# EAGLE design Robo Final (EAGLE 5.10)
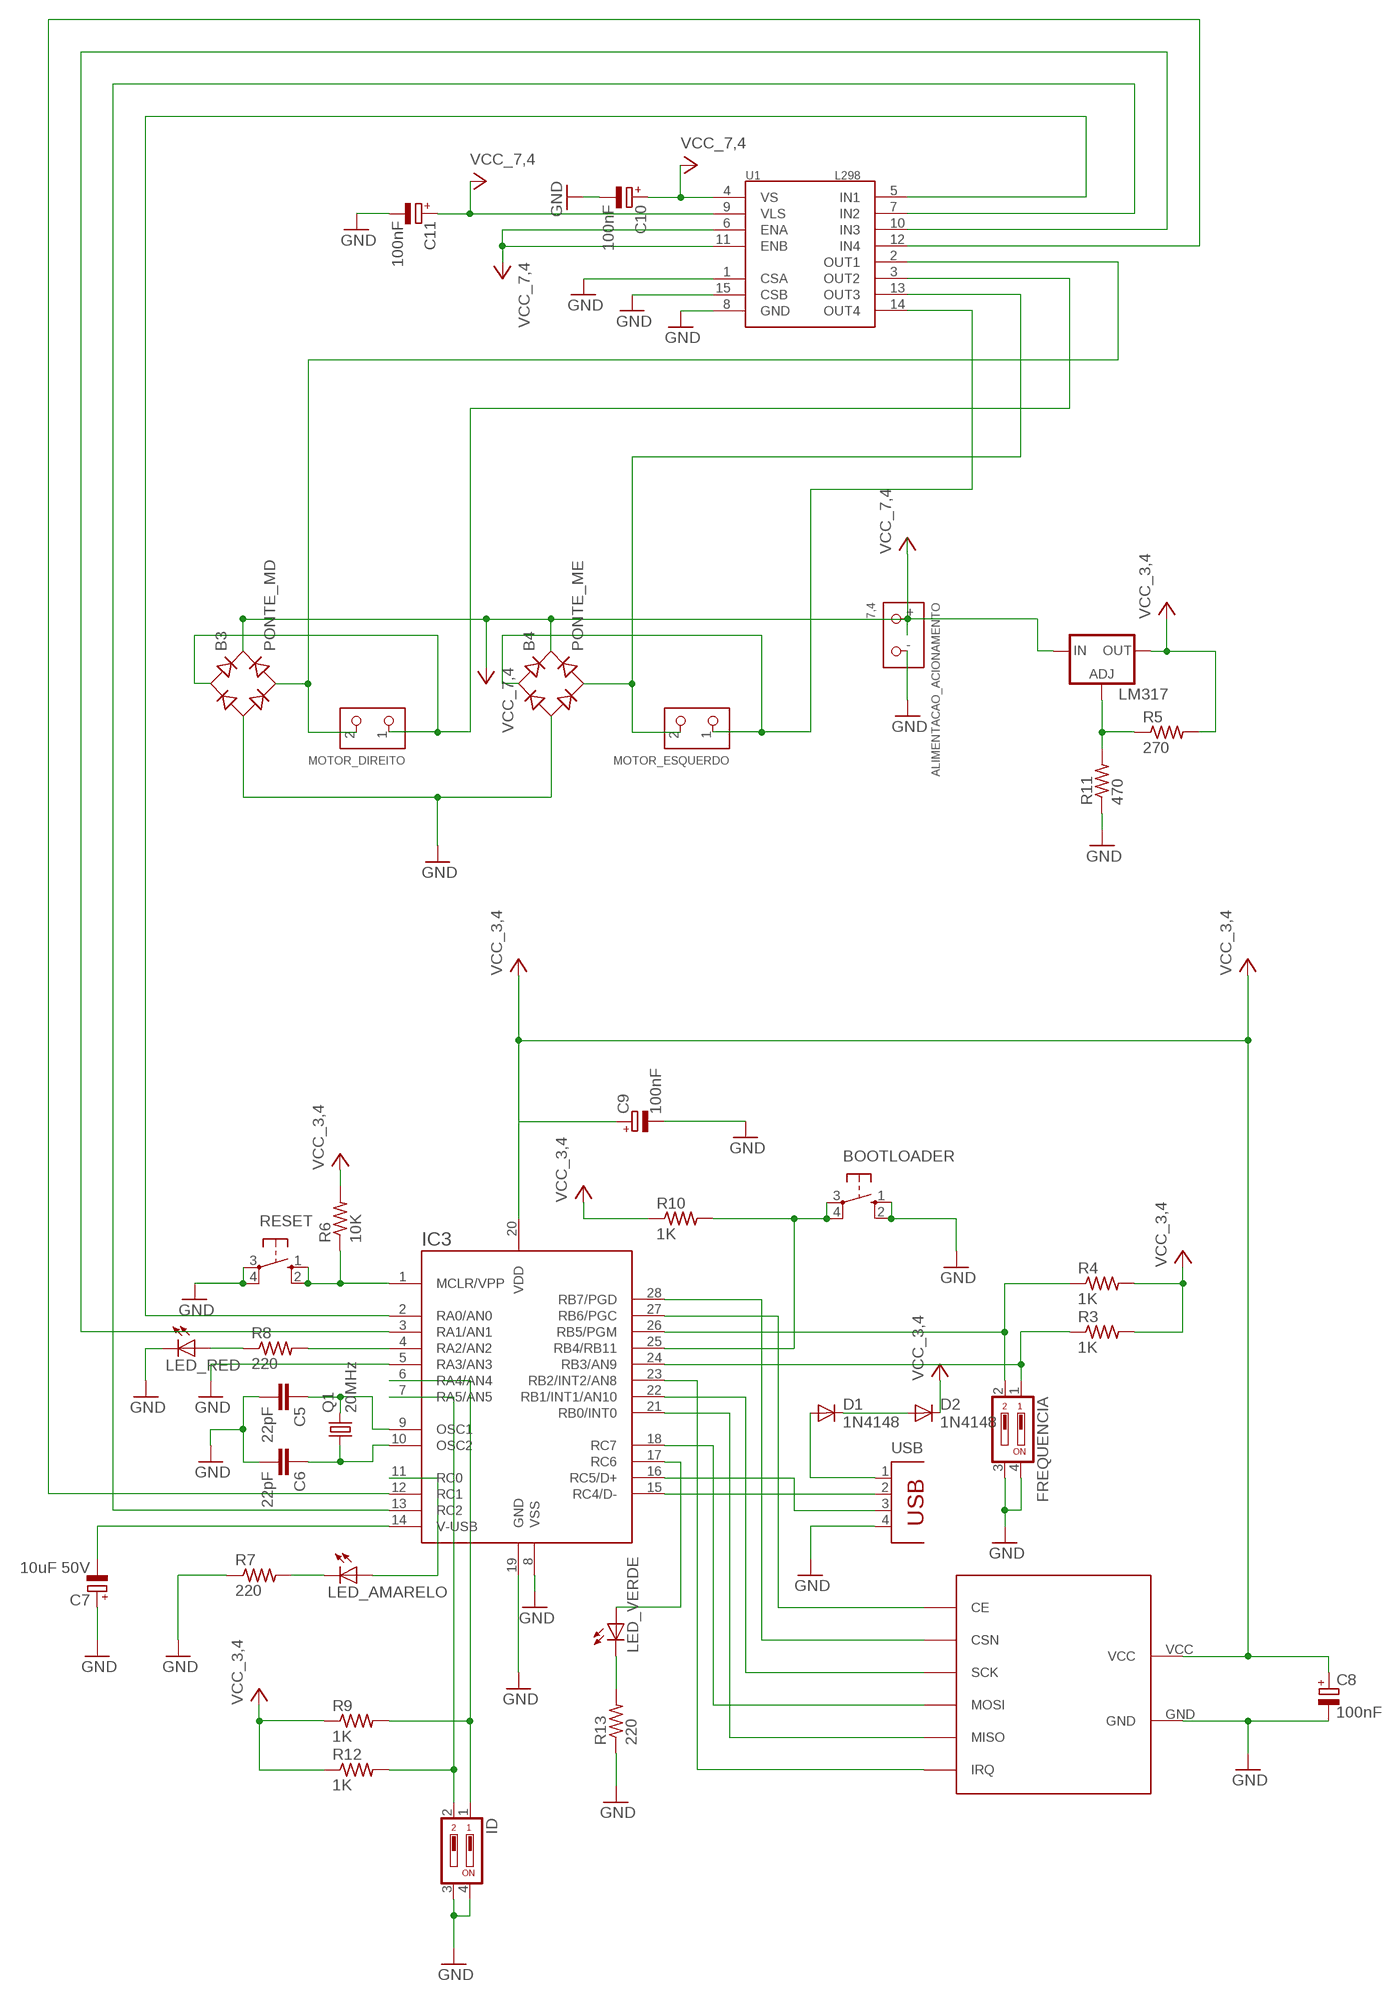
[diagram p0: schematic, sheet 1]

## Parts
ALIMENTACAO_ACIONAMENTO  7,4  PIN_HEADER/2_POWER  [22-04-1021/2-POWER]
B3  PONTE_MD  B-DIL  [B-DIL]
B4  PONTE_ME  B-DIL  [B-DIL]
BOOTLOADER  10-XX  [B3F-10XX]
C5  22pF  C2.5/2  [C2.5-2]
C6  22pF  C2.5/2  [C2.5-2]
C7  10uF 50V  CPOL-EUE3.5-10  [E3,5-10]
C8  100nF  CPOL-EUE2.5-6  [E2,5-6]
C9  100nF  CPOL-EUE2.5-6  [E2,5-6]
C10  100nF  CPOL-EUE2.5-6  [E2,5-6]
C11  100nF  CPOL-EUE2.5-6  [E2,5-6]
D1  1N4148  1N4148DO35-7  [DO35-7]
D2  1N4148  1N4148DO35-7  [DO35-7]
FREQUENCIA  DIP02YL  [DIP02YL]
IC3  PIC18F2550DIL-28  [DIL28]
ID  DIP02YL  [DIP02YL]
LED_AMARELO  LED3MM  [LED3MM]
LED_RED  LED3MM  [LED3MM]
LED_VERDE  LED3MM  [LED3MM]
LM317  LM317TS  [317TS]
MOTOR_DIREITO  PIN_HEADER/2  [22-04-1021/2]
MOTOR_ESQUERDO  PIN_HEADER/2  [22-04-1021/2]
NRF24L1  NFR24L01+  [NRF24L01_V2]
Q1  20MHz  CRYSTALHC49S  [HC49/S]
R3  1K  R-US_0207/7  [0207/7]
R4  1K  R-US_0207/7  [0207/7]
R5  270  R-US_0207/7  [0207/7]
R6  10K  R-US_0207/7  [0207/7]
R7  220  R-US_0207/7  [0207/7]
R8  220  R-US_0207/15  [0207/15]
R9  1K  R-US_0207/10  [0207/10]
R10  1K  R-US_0207/10  [0207/10]
R11  470  R-US_0207/7  [0207/7]
R12  1K  R-US_0207/7  [0207/7]
R13  220  R-US_0207/7  [0207/7]
RESET  10-XX  [B3F-10XX]
U1  L298  [MULTIWATT15]
USB  PN87520  [PN87520]

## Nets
CE: IC3.27(RB6/PGC) NRF24L1.CE
CSN: IC3.28(RB7/PGD) NRF24L1.CSN
FREQ1: FREQUENCIA.2 IC3.26(RB5/PGM) R4.1
FRQ0: FREQUENCIA.1 IC3.24(RB3/AN9) R3.1
GND: ALIMENTACAO_ACIONAMENTO.- B3.- B4.- BOOTLOADER.1(S) BOOTLOADER.2(S1) C5.2 C6.2 C7.+ C8.- C9.- C10.- C11.- FREQUENCIA.3 FREQUENCIA.4 IC3.5(RA3/AN3) IC3.8(VSS) IC3.19(GND) ID.3 ID.4 LED_RED.K(C) NRF24L1.GND R7.1 R11.1 R13.1 RESET.3(P) RESET.4(P1) U1.1(CSA) U1.8(GND) U1.15(CSB) USB.4
ID0: IC3.6(RA4/AN4) ID.1 R9.2
ID1: IC3.7(RA5/AN5) ID.2 R12.2
IRQ: IC3.23(RB2/INT2/AN8) NRF24L1.IRQ
MISO: IC3.21(RB0/INT0) NRF24L1.MISO
MOSI: IC3.18(RC7) NRF24L1.MOSI
N$1: IC3.4(RA2/AN2) R8.2
N$2(+): B4.AC1 MOTOR_ESQUERDO.1 U1.14(OUT4)
N$3(+): B3.AC1 MOTOR_DIREITO.1 U1.3(OUT2)
N$4: BOOTLOADER.3(P) BOOTLOADER.4(P1) IC3.25(RB4/RB11) R10.2
N$5: C7.- IC3.14(V-USB)
N$11: IC3.1(MCLR/VPP) R6.1 RESET.1(S) RESET.2(S1)
N$12(-): B4.AC2 MOTOR_ESQUERDO.2 U1.13(OUT3)
N$15: LM317.1(ADJ) R5.1 R11.2
N$16: C5.1 IC3.9(OSC1) Q1.2
N$17: IC3.15(RC4/D-) USB.2
N$18: C6.1 IC3.10(OSC2) Q1.1
N$19(-): B3.AC2 MOTOR_DIREITO.2 U1.2(OUT1)
N$20: IC3.16(RC5/D+) USB.3
N$21: IC3.12(RC1) U1.12(IN4)
N$24: IC3.13(RC2) U1.7(IN2)
N$25: D1.A USB.1
N$27: LED_AMARELO.K(C) R7.2
N$28: LED_VERDE.K(C) R13.2
N$29: IC3.11(RC0) LED_AMARELO.A
N$30: IC3.17(RC6) LED_VERDE.A
N$31: D1.C D2.A
N$43: LED_RED.A R8.1
SCK: IC3.22(RB1/INT1/AN10) NRF24L1.SCK
SENTIDO_DIREITO: IC3.2(RA0/AN0) U1.5(IN1)
SENTIDO_ESQUERDO: IC3.3(RA1/AN1) U1.10(IN3)
VCC_3,4: C8.+ C9.+ D2.C IC3.20(VDD) LM317.2(OUT) NRF24L1.VCC R3.2 R4.2 R5.2 R6.2 R9.1 R10.1 R12.1
VCC_7,4: ALIMENTACAO_ACIONAMENTO.+ B3.+ B4.+ C10.+ C11.+ LM317.3(IN) U1.4(VS) U1.6(ENA) U1.9(VLS) U1.11(ENB)

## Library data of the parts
ALIMENTACAO_ACIONAMENTO = Futebol_de_robos:PIN_HEADER/2_POWER: Connector de 2 pinos para alimentação
B3 B4 = rectifier:B-DIL: RECTIFIER
BOOTLOADER RESET = switch-omron:10-XX: OMRON SWITCH
C5 C6 = capacitor-wima:C: CAPACITOR
C7-C11 = rcl:CPOL-EU: POLARIZED CAPACITOR, European symbol
D1 D2 = diode:1N4148: DIODE
FREQUENCIA ID = switch-dil:DIP02YL: DIL/CODE SWITCH
IC3 = pic18f2550_3:PIC18F2550: PIC18F2550 Richard Myrick T. Arellaga April 2010
LED_AMARELO LED_RED LED_VERDE = led:LED: LED
LM317 = v-reg:LM317TS: VOLTAGE REGULATOR
MOTOR_DIREITO MOTOR_ESQUERDO = Futebol_de_robos:PIN_HEADER/2: Connector de 2 pinos
NRF24L1 = novo_transciever_v2:NFR24L01+: Transceiver nRF24L01+ para ser usado no futebol de robôs. Opera na faixa de 2.4 GHz.
Q1 = crystal:CRYSTAL: CRYSTAL
R3-R13 = resistor:R-US_: RESISTOR, American symbol
U1 = SparkFun_v2:L298: L298 Dual Full Bridge Driver
USB = con-berg:PN87520: BERG USB connector

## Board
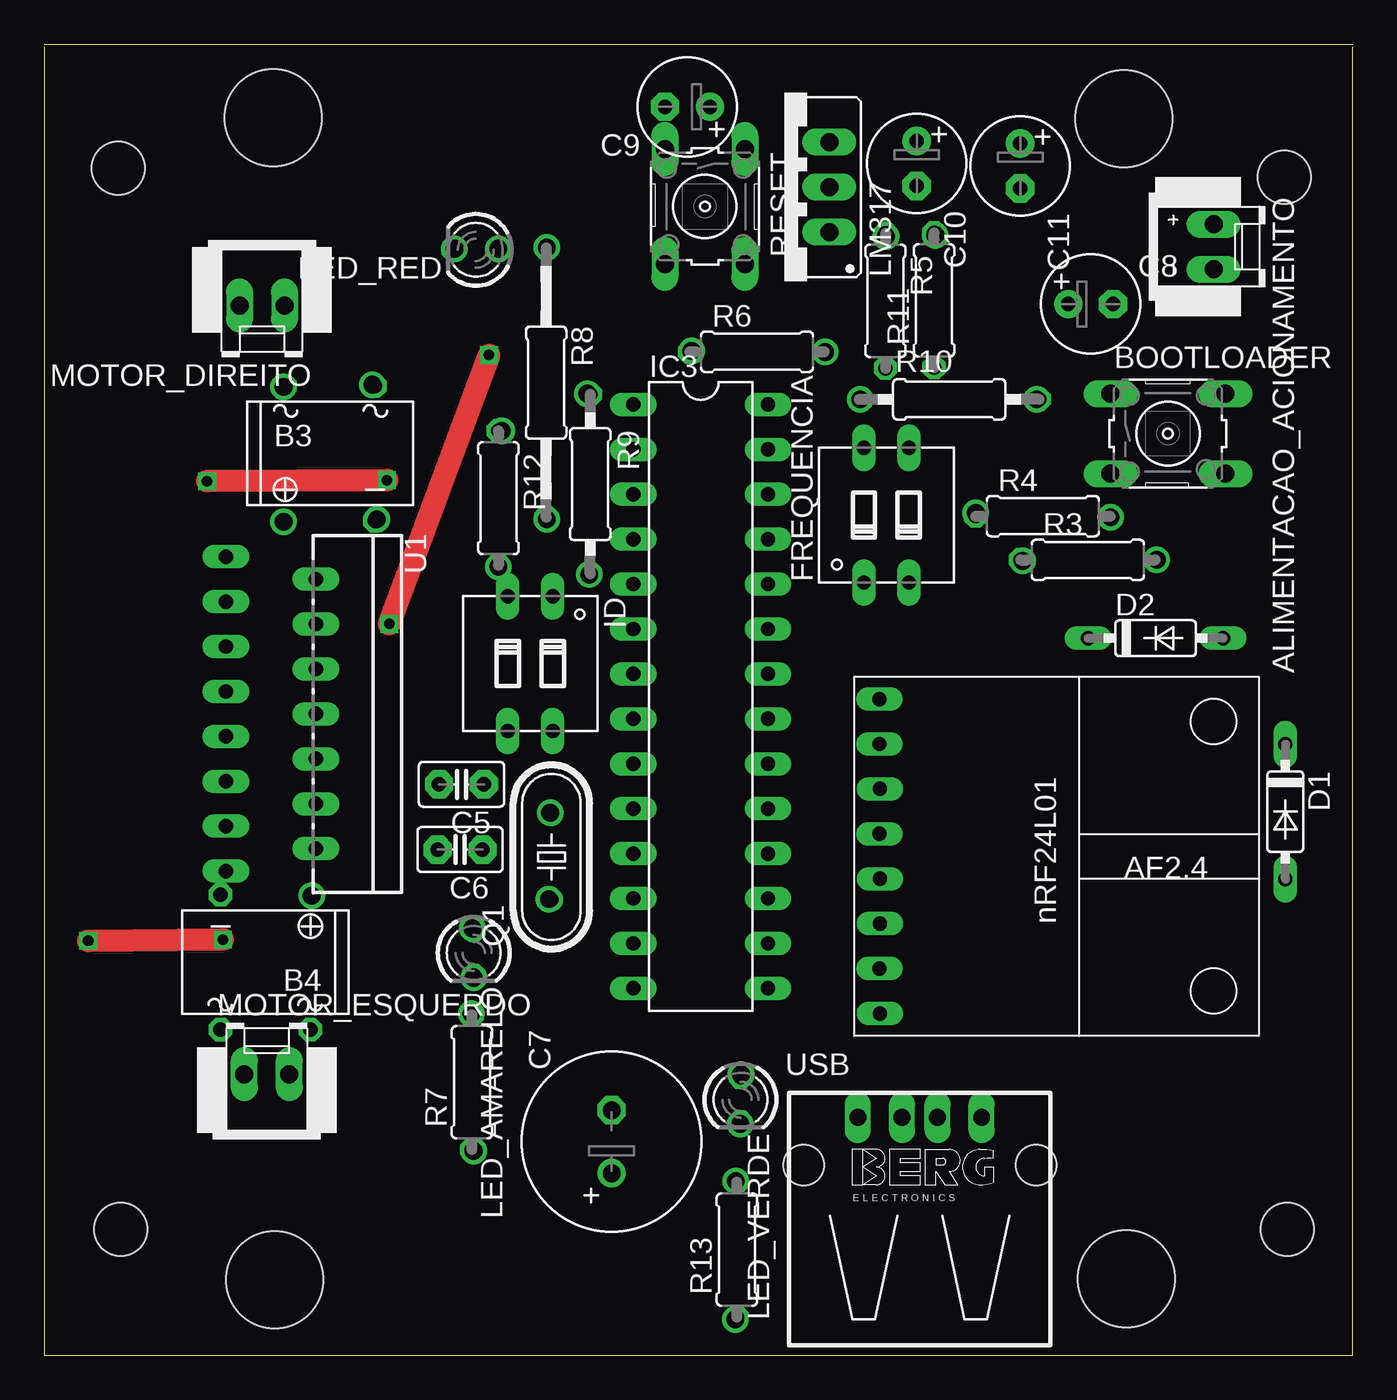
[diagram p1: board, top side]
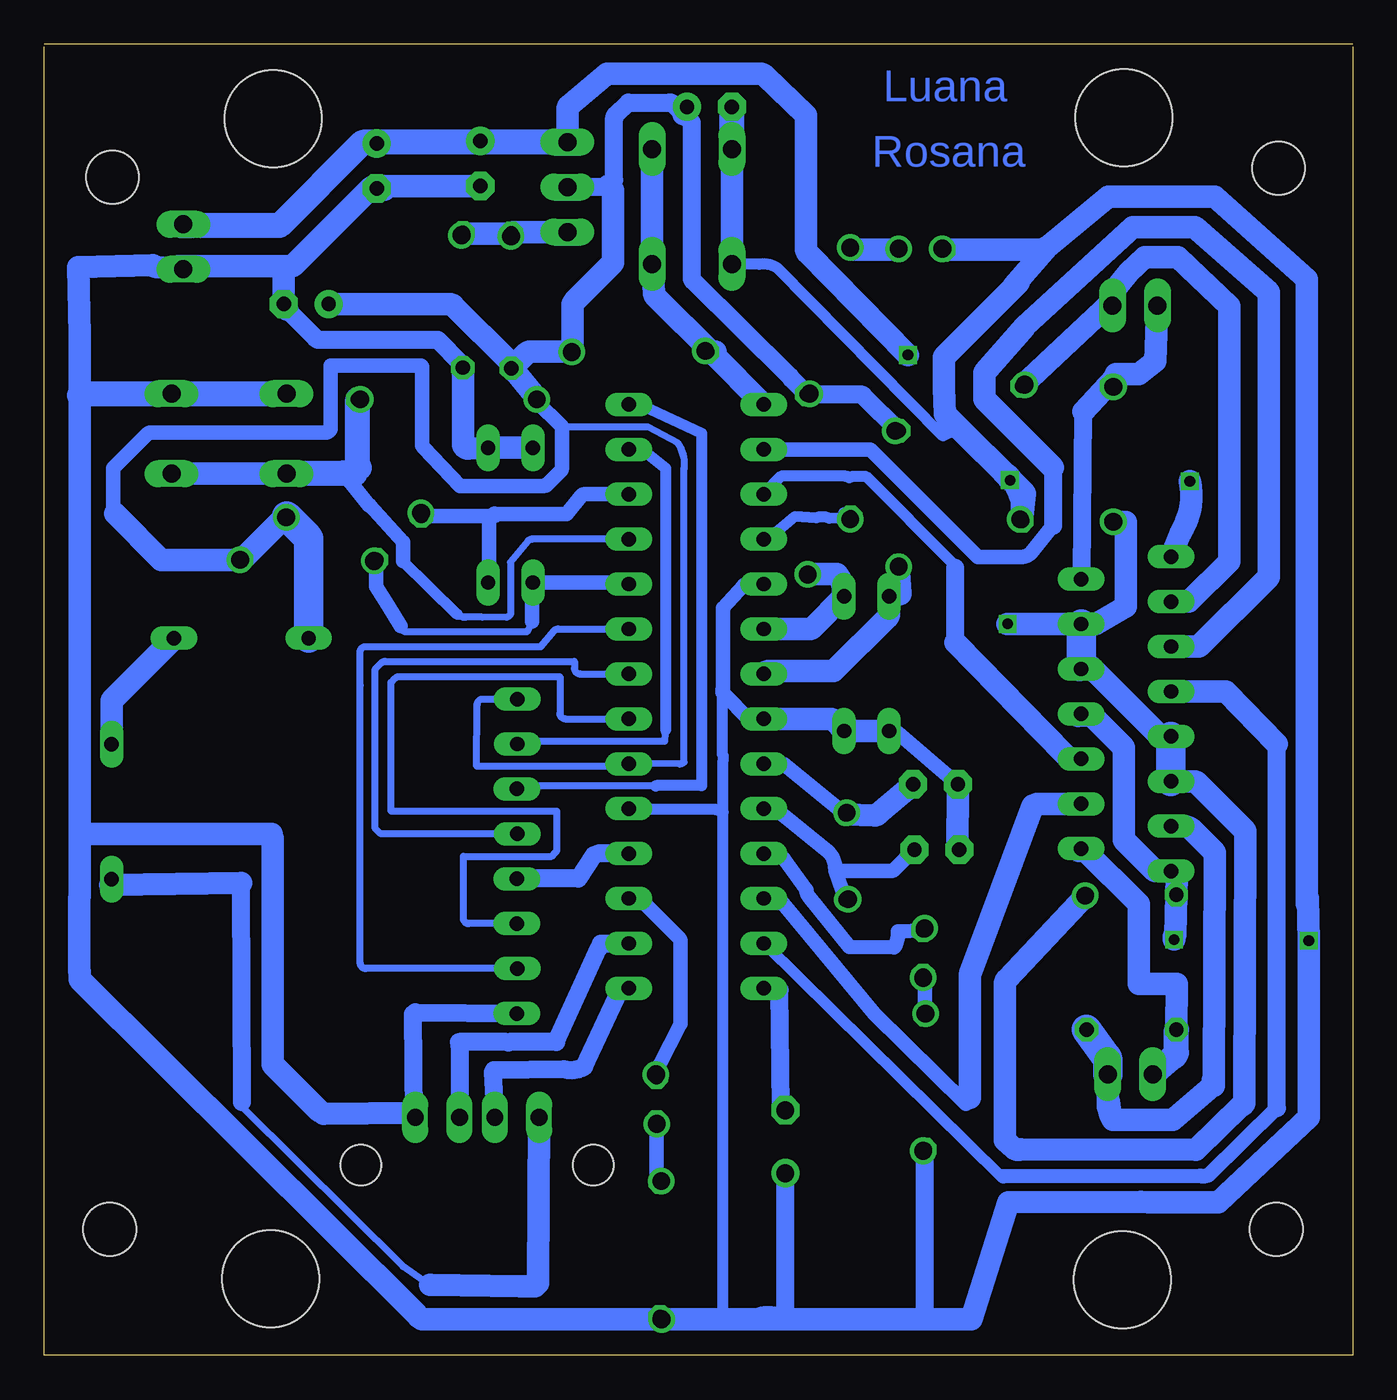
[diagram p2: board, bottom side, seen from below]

Size 74 x 74.15 mm. Coordinates in mm from the lower left corner, seen from the top.
Outline: 74,74 74,0 0,0 0,74
Outline: 0,74.15 74,74.15
Copper layers (1*16): Top 0.035mm / dielectric 1.5mm / Bottom 0.035mm
Design rules "default *": minimum track width 10mil, minimum drill 24mil, track to track 16mil, track to pad 16mil, pad to pad 16mil, via to via 16mil, smd to smd 8mil, copper to edge 40mil, drill to drill 8mil, minimum pad ring 10mil, minimum via ring 8mil, stop-mask expansion 4mil, vias tented up to drill 0mil, thermal gap 10mil
Holes 5.5 mm at 12.95,69.99 61.06,69.92 13.03,4.26 61.2,4.32
Holes 3 mm at 4.19,67.13 70.14,66.62 4.32,7.12 70.29,7.12

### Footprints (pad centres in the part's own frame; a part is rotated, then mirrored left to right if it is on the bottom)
22-04-1021/2-POWER = drill 1.016 pad 1.524 long: + -1.27,0; - 1.27,0
B-DIL = drill 0.813 round: + -2.54,-3.81 | drill 0.813 octagon: - 2.54,-3.81; AC1 2.54,3.81; AC2 -2.54,3.81
B3F-10XX = drill 1.016 long: 1 -3.251,2.261; 2 3.251,2.261; 3 -3.251,-2.261; 4 3.251,-2.261
C2.5-2 = drill 0.813 pad 1.6 octagon: 1 -1.27,0; 2 1.27,0
E3,5-10 = drill 0.813 pad 1.6 round: + -1.778,0 | drill 0.813 pad 1.6 octagon: - 1.778,0
E2,5-6 = drill 0.813 pad 1.6 round: + -1.27,0 | drill 0.813 pad 1.6 octagon: - 1.27,0
DO35-7 = drill 0.813 long: A 3.81,0; C -3.81,0
DIP02YL = drill 0.813 long: 1 -1.27,-3.81; 2 1.27,-3.81; 3 1.27,3.81; 4 -1.27,3.81
DIL28 = drill 0.813 long: 1 -16.51,-3.81; 2 -13.97,-3.81; 3 -11.43,-3.81; 4 -8.89,-3.81; 5 -6.35,-3.81; 6 -3.81,-3.81; 7 -1.27,-3.81; 8 1.27,-3.81; 9 3.81,-3.81; 10 6.35,-3.81; 11 8.89,-3.81; 12 11.43,-3.81; 13 13.97,-3.81; 14 16.51,-3.81; 15 16.51,3.81; 16 13.97,3.81; 17 11.43,3.81; 18 8.89,3.81; 19 6.35,3.81; 20 3.81,3.81; 21 1.27,3.81; 22 -1.27,3.81; 23 -3.81,3.81; 24 -6.35,3.81; 25 -8.89,3.81; 26 -11.43,3.81; 27 -13.97,3.81; 28 -16.51,3.81
LED3MM = drill 0.813 octagon: A -1.27,0; K 1.27,0
317TS = drill 1.016 long: 1 -2.54,-2.54; 2 0,-2.54; 3 2.54,-2.54
22-04-1021/2 = drill 1.016 pad 1.524 long: 1 -1.27,0; 2 1.27,0
NRF24L01_V2 = drill 0.813 long: CE 1.422,16.51; CSN 1.448,13.97; GND 1.448,1.27; IRQ 1.422,3.81; MISO 1.448,6.35; MOSI 1.448,8.89; SCK 1.422,11.43; VCC 1.422,19.05
HC49/S = drill 0.813 round: 1 -2.413,0; 2 2.413,0
0207/7 = drill 0.813 octagon: 1 -3.81,0; 2 3.81,0
0207/15 = drill 0.813 octagon: 1 -7.62,0; 2 7.62,0
0207/10 = drill 0.813 octagon: 1 -5.08,0; 2 5.08,0
MULTIWATT15 = drill 0.813 long: 1 -8.95,-2.39; 2 -7.68,2.69; 3 -6.41,-2.39; 4 -5.14,2.69; 5 -3.87,-2.39; 6 -2.6,2.69; 7 -1.33,-2.39; 8 -0.06,2.69; 9 1.21,-2.39; 10 2.48,2.69; 11 3.75,-2.39; 12 5.02,2.69; 13 6.29,-2.39; 14 7.56,2.69; 15 8.83,-2.39
PN87520 = drill 0.95 long: 1 -3.5,2.71; 2 -1,2.71; 3 1,2.71; 4 3.5,2.71 | hole 2.3: -6.57,0; 6.57,0

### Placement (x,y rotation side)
ALIMENTACAO_ACIONAMENTO  66.14,62.69 270 top
B3  16.17,51 0 top
B4  12.51,22.24 180 top
BOOTLOADER  63.55,52.12 0 top
C5  23.6,32.29 180 top
C6  23.52,28.6 180 top
C7  32.08,12.08 90 top
C8  59.18,59.45 0 top
C9  36.38,70.61 180 top
C10  49.34,67.4 270 top
C11  55.2,67.26 270 top
D1  70.19,30.74 270 top
D2  62.85,40.55 0 top
FREQUENCIA  47.63,47.51 0 top
IC3  37.12,37.26 270 top
ID  27.49,39.12 180 top
LED_AMARELO  24.29,22.76 270 top
LED_RED  24.41,62.52 180 top
LED_VERDE  39.38,14.46 270 top
LM317  41.87,66.07 90 top
MOTOR_DIREITO  12.32,59.37 180 top
MOTOR_ESQUERDO  12.59,15.89 0 top
NRF24L1  45.81,18.06 0 top
Q1  28.68,28.19 90 top
R3  59.02,44.98 0 top
R4  56.48,47.46 0 top
R5  47.57,59.63 270 top
R6  40.31,56.75 0 top
R7  24.19,15.44 90 top
R8  28.38,55.01 270 top
R9  30.88,49.27 270 top
R10  51.18,54.06 0 top
R11  50.32,59.66 90 top
R12  25.69,48.47 270 top
R13  39.17,5.98 90 top
RESET  37.37,64.97 270 top
U1  12.67,36.21 270 top
USB  49.51,10.74 0 top

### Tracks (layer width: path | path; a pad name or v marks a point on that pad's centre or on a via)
CE
  Bottom 0.4: 38.91,34.72 47.25,34.72
  Bottom 0.406: 47.25,34.72 47.25,34.58 arc-90 NRF24L1.CE | 38.84,35.37 arc-90 38.9,35.19 38.91,34.72
  Bottom 0.61: IC3.27 40.31,51.23 arc45 40.09,51.14 38.84,50.16 38.84,35.37
CSN
  Bottom 0.4: 39.42,32.19 46.5,32.19
  Bottom 0.406: NRF24L1.CSN 46.79,32.03 arc-45 46.56,32.12 46.5,32.19
  Bottom 0.61: IC3.28 40.36,53.77 arc45 40.13,53.68 36.8,52.13 36.8,32.28 arc45 36.83,32.22 39.35,32.22 arc-45 39.42,32.19
FREQ1
  Bottom 0.813: 48.6,47.55 48.85,47.31 48.85,43.83 arc45 FREQUENCIA.2 | IC3.26 43.41,48.69 arc-45 43.63,48.6 44.46,47.59 45.38,47.59 arc47 45.44,47.59 48.31,47.59 arc-45 48.47,47.49 48.54,47.62 48.6,47.55 | R4.1 48.83,47.46 arc-45 48.6,47.55
FRQ0
  Bottom 0.406: 46.41,41.5 46.71,40.91 51.66,40.91 53.52,40.91 arc90 53.84,41.23
  Bottom 0.813: IC3.24 arc-45 41.15,43.7 FREQUENCIA.1 arc-90 46.41,43.65 46.41,41.5 | R3.1 arc-45 55.22,44.96 55.22,43.47 54.54,42.39 53.84,41.23
GND  (via drill 0.6)
  Top 1.27: v19.38,49.49 v9.21,49.43 | v2.49,23.44 v10.1,23.51
  Bottom 0.406: 53.14,19.3 arc45 53,19.39 | USB.4 arc-45 53.07,13.47
  Bottom 0.61: RESET.4 33.56,61.7 arc45 32.54,61.48 23.17,51.99 22.27,52.38 arc45 23.1,54.47 23.12,54.69 | 35.64,37.47 35.64,33.99 arc45 35.61,33.64 35.61,30.7 | IC3.19 arc-45 40.81,30.86 36.02,30.86 arc45 35.8,30.77 35.61,30.7 | 35.61,30.7 35.61,2.34 arc45 35.83,2.11 35.91,2.03
  Bottom 0.813: 33.17,35.93 arc45 IC3.8 33.33,35.98 arc45 33.55,35.88 34.06,35.88 35.64,37.47 arc45 35.61,37.69 35.61,42.25 34.46,43.52 arc45 34.24,43.61 IC3.5 | C5.2 25.76,35.22 arc-45 25.98,35.31 ID.3 | 58.42,13.8 arc-45 58.2,13.65 | 61.14,29.48 arc45 61.08,29.26 | 72,29.48 arc-53 71.85,29.48
  Bottom 1.016: U1.8 15.52,36.11 15.52,36.02 | 60.27,59.14 58.66,57.52 arc-45 58.43,57.43 51.75,57.43 50.42,56.09 arc45 50.32,55.87 R11.1 | C7.+ 32.08,2.03 arc-45 33.58,2.2 33.41,2.03 | R7.1 24.19,2.24 arc45 24.28,2.03 | R13.1 41.23,2.07 arc-45 41.22,2.03 | 53,19.39 NRF24L1.GND | 53.07,13.47 53.14,19.3
  Bottom 1.27: 17.27,62.66 13.81,65.53 7.79,65.53 2.6,60.85 2.6,25.53 arc-45 2.55,25.86 v2.49,23.44 2.49,13.46 7.61,8.65 11.57,8.65 11.98,8.69 19.46,8.65 21.58,2.03 24.28,2.03 33.41,2.03 35.91,2.03 41.22,2.03 52.58,2.03 arc45 52.94,2.32 71.99,21.25 71.98,21.67 arc-45 72.01,21.72 72.01,25.88 72,25.95 72,29.48 72,54.3 72,57.7 72.09,61.55 67.87,61.64 arc-45 67.64,61.55 ALIMENTACAO_ACIONAMENTO.- arc45 66.41,61.6 60.41,61.6 | 17.27,62.66 19.17,60.5 18.86,60.7 23.12,56.44 23.12,54.69 23.06,53.23 18.55,48.72 B3.- 18.71,48.25 arc-45 19.95,50.12 v19.38,49.49 | 15.33,36.24 U1.8 15.27,36.18 14.74,36.18 12.93,34.38 12.93,29.13 11.18,27.38 U1.15 9.94,27.04 B4.- 10.04,23.76 arc-90 v10.1,23.51 | 26.15,35.28 arc-45 ID.3 ID.4 29.35,35.9 arc-45 29.57,35.99 IC3.8 | C6.2 22.32,28.65 arc-45 22.36,28.5 C5.2 | RESET.4 RESET.3 | LED_RED.K 17.5,62.52 arc45 17.27,62.66 | 54.84,66.13 arc-45 54.74,65.91 C11.- | C10.- 54.91,66.13 arc-45 C11.- | C11.- 55.3,66.11 arc-45 55.52,66.02 59.95,61.6 60.41,61.6 | R11.1 50.32,51.59 arc-90 50.01,51.28 FREQUENCIA.3 FREQUENCIA.4 | 60.41,61.6 arc-45 60.45,61.5 C8.- 60.37,59.36 arc45 60.27,59.14 | v9.21,49.43 arc45 9.75,46.48 U1.1 | 58.2,13.65 53.13,13.72 53.13,13.51 arc-90 USB.4 | 58.42,13.8 61.08,16.45 61.08,29.26 | 71.85,29.48 61.14,29.48
  Bottom 1.422: C9.- arc45 35.1,70.6 RESET.3 | BOOTLOADER.1 BOOTLOADER.2 71.8,54.38 arc-45 72,54.3
ID0
  Bottom 1.27: R9.2 29.17,44.17 arc45 28.82,43.19 ID.1 30.52,41.17 arc45 30.75,41.07 IC3.6
ID1
  Bottom 1.27: R12.2 25.58,43.06 arc45 26.12,43.03 ID.2 26.22,41.96 arc45 26.31,41.73 29.36,38.69 33.03,38.69 arc-45 33.25,38.6 IC3.7
IRQ
  Bottom 0.406: IC3.23 44.93,41.07 arc-45 45.16,40.98 45.92,40.08 55.82,40.08 arc-90 56.14,39.76 56.14,39.7 56.13,37.89 56.13,22.19 arc-90 55.81,21.87 NRF24L1.IRQ
MISO
  Bottom 0.4: 50.3,28.22 45.3,28.22 | 45.55,30.76 50.45,30.76
  Bottom 0.406: NRF24L1.MISO 49.98,24.41 arc90 50.3,24.73 50.3,28.22 | IC3.21 44.52,35.99 arc90 44.84,36.31 44.84,38.38 53.92,38.38 arc-45 54.15,38.29 54.38,38.05 54.38,30.8 arc-45 54.28,30.76 50.45,30.76 | 45.55,30.76 45.01,30.77 45.01,28.65 arc45 45.1,28.43 45.3,28.22
MOSI
  Bottom 0.406: 42.7,28.37 arc-45 42.92,28.28 | 47.08,26.96 arc45 NRF24L1.MOSI
  Bottom 1.016: IC3.18 42.7,28.37 | 42.92,28.28 43.78,26.96 47.08,26.96
N$1
  Bottom 0.61: 28.79,47.66 arc45 28.56,47.56 R8.2 29.6,47.33 arc-45 30.33,47.36 31.56,47.42 32.99,46.25 arc45 33.22,46.15 IC3.4
N$2  (via drill 0.6 pad 5.5)
  other vias: 61.06,69.94
N$2(+)
  Bottom 1.27: B4.AC1 9.94,21.01 12.09,21 12.1,25.53 15.19,28.61 15.5,28.51 U1.14
  Bottom 1.422: B4.AC1 9.97,17.11 arc45 10.13,16.89 MOTOR_ESQUERDO.1
N$3  (via drill 1)
  other vias: 28.42,62.64
N$3(+)
  Bottom 1.27: U1.3 9.27,42.62 6.99,44.9 6.99,59.33 9.9,62.1 11.75,62.1 12.66,61.27 13.52,60.21 MOTOR_DIREITO.1 13.69,59.52 B3.AC1
N$4
  Bottom 0.406: IC3.25 46.41,46.15 arc-45 46.63,46.06 47.63,44.85 47.63,41.9 arc45 47.86,41.73 49.24,41.74 50.14,41.74 arc45 50.64,41.9 | 55.6,48.09 arc45 55.63,48.07 | 53.74,44.91 arc-45 53.7,44.92
  Bottom 0.61: 50.64,41.9 53.74,44.91
  Bottom 0.813: 55.63,48.07 57.09,49.89 | 55.6,48.09 53.7,46 53.7,44.92
  Bottom 1.27: BOOTLOADER.3 BOOTLOADER.4
  Bottom 1.422: BOOTLOADER.3 56.43,49.86 arc45 56.78,49.83 | 57.09,49.89 56.78,49.83 | R10.2 56.26,50.41 arc-45 56.17,50.18 56.78,49.83
N$5
  Bottom 0.406: 32.41,20.66 arc-45 32.51,20.75
  Bottom 0.813: 32.51,20.75 IC3.14
  Bottom 1.016: C7.- 32.34,14.01 32.41,20.66
N$6  (via drill 0.6 pad 3)
  other vias: 70.15,66.63
N$7  (via drill 0.6 pad 5.5)
  other vias: 13.04,4.26
N$8  (via drill 0.6 pad 5.5)
  other vias: 61.2,4.32
N$9  (via drill 0.6 pad 5.5)
  other vias: 12.96,70
N$10  (via drill 0.6 pad 3)
  other vias: 4.31,7.13
N$11
  Bottom 1.27: IC3.1 36.21,56.67 | 36.21,56.67 39.42,59.88 arc45 39.51,60.1 RESET.2 RESET.1 | R6.1 36.03,56.75 arc-45 36.21,56.67
N$12  (via drill 0.6 pad 3)
  other vias: 4.15,67.12
N$12(-)
  Bottom 1.27: U1.13 9.54,29.92 arc45 9.08,29.71 7.81,28.44 7.85,15.23 7.91,15.59 arc45 8.01,15.17 10.18,13.32 13.57,13.32 arc44 13.8,14.37 13.75,13.92 13.76,13.94 arc45 13.86,14.16 MOTOR_ESQUERDO.2
  Bottom 1.676: MOTOR_ESQUERDO.2 13.86,16.68 arc-45 13.95,16.91 B4.AC2
N$13  (via drill 0.6 pad 3)
  other vias: 70.31,7.14
N$14  (via drill 1)
  other vias: 25.69,62.58
N$15
  Bottom 1.27: LM317.1 47.38,63.53 arc-45 R5.1 50.26,63.44 arc45 R11.2
N$16
  Bottom 0.813: Q1.2 32.08,33.36 arc-45 32.31,33.45 IC3.9
  Bottom 1.27: C5.1 26.83,30.63 arc45 27.05,30.54 Q1.2
N$17
  Bottom 0.406: 41.43,20.66 arc45 41.21,20.75 | 48.56,16.12 arc-45 48.64,16.01
  Bottom 1.016: 41.21,20.75 IC3.15 | 41.43,20.66 43.47,16.32 arc45 44.61,16.18 48.56,16.12 | 48.64,16.01 USB.2
N$18
  Bottom 0.813: 33.2,30.96 arc-45 IC3.10 arc45 33.29,30.93 32.66,30.93 29.67,28.5 arc45 29.26,27.39 | 29.26,27.39 Q1.1 | 29.26,27.39 26.13,27.39 arc-45 25.91,27.48 C6.1
N$19  (via drill 1)
  other vias: 23.21,62.58
N$19(-)
  Bottom 1.016: 15.32,44.09 15.23,53.37
  Bottom 1.27: U1.2 15.33,43.89 arc-90 15.32,44.09 | MOTOR_DIREITO.2 11.17,56.21 12.09,55.48 13.4,55.48 B3.AC2 13.47,55.26 15.23,53.37
N$20
  Bottom 0.406: 42.62,23.06 arc-45 42.53,23.28 | 50.55,17.71 arc-45 50.52,17.52 | 47.76,17.67 arc45 47.85,17.71
  Bottom 1.016: 42.53,23.28 IC3.16 | 42.62,23.06 45.05,17.71 47.72,17.71 47.76,17.67 | 50.52,17.52 USB.3 | 47.85,17.71 50.55,17.71
N$21
  Bottom 0.813: 18.08,31.1 arc45 17.86,31.19 | IC3.12 33.15,25.67 arc-45 32.93,25.58 32.52,25.58 arc45 32.23,25.55 27.06,19.29 21.88,14.21 21.75,14.34 arc-45 21.66,14.57
  Bottom 1.27: 17.86,31.19 U1.12 | 18.08,31.1 21.66,21.55 21.66,14.57
N$22  (via drill 1)
  other vias: 24.29,11.56
N$23  (via drill 1)
  other vias: 24.16,19.31
N$24
  Bottom 0.61: 32.8,23.05 32.94,23.05 arc45 33.17,23.15 IC3.13 | 19.77,10.12 arc-45 19.83,10.07 33.2,23.25 arc-45 IC3.13 | 32.98,23.1 arc45 33.21,23.19 IC3.13
  Bottom 0.813: 4.29,13.99 8.12,10.21 arc45 8.64,10.15 19.77,10.12
  Bottom 1.016: 4.29,13.99 4.29,34.56
  Bottom 1.27: U1.7 7.18,37.54 4.29,34.56
N$25
  Bottom 0.406: 52.05,3.87 53.7,5.02 62.73,13.98 62.73,14.25 arc-90 62.8,14.33 | 46.24,3.92 arc-45 46.08,4.07 | 52.18,3.98 arc45 52.21,3.93
  Bottom 1.016: 52.21,3.93 52.18,4.12 arc90 52.05,3.87 | 62.8,14.33 62.87,26.72
  Bottom 1.27: 46.08,4.07 USB.1 | 46.24,3.92 47.1,3.91 52.18,3.98 | 62.87,26.72 70.27,26.6 D1.A
N$26  (via drill 1)
  other vias: 24.29,21.35
N$27
  Bottom 0.813: R7.2 24.19,20.94 arc-45 24.28,21.16 LED_AMARELO.K
N$28
  Bottom 0.813: LED_VERDE.K 39.38,10.12 arc-45 39.28,9.9 R13.2
N$29
  Bottom 0.813: IC3.11 32.65,28.37 arc45 32.42,28.28 32.16,28.08 30.89,26.31 arc-45 30.73,25.89 28.47,23.09 25.96,23.06 arc-45 25.73,23.98 LED_AMARELO.A
N$30
  Bottom 0.406: LED_VERDE.A 39.38,16.13 arc45 39.28,16.36 39.22,16.42
  Bottom 0.813: 39.22,16.42 38.02,18.75 38.02,23.39 arc-45 38.11,23.61 40.44,25.94 40.7,25.94 arc-45 40.92,25.85 IC3.17
N$31
  Bottom 1.27: D1.C 70.19,37.03 D2.A
N$32  (via drill 1)
  other vias: 39.1,9.85
N$33  (via drill 1)
  other vias: 39.36,13.09
N$34  (via drill 1)
  other vias: 28.61,30.69
N$35  (via drill 1)
  other vias: 28.53,25.79
N$36  (via drill 1)
  other vias: 28.42,47.27
N$37  (via drill 1)
  other vias: 30.71,54.38
N$38  (via drill 1)
  other vias: 25.88,52.29
N$39  (via drill 1)
  other vias: 50.4,63.34
N$40  (via drill 1)
  other vias: 47.6,63.28
N$41  (via drill 1)
  other vias: 44.17,56.74
N$42  (via drill 1)
  other vias: 36.61,56.8
N$43
  Bottom 1.27: LED_RED.A 28.14,62.52 arc45 28.36,62.61 R8.1
N$44  (via drill 1)
  other vias: 46.14,54.07
N$45  (via drill 1)
  other vias: 52.69,47.65
N$46  (via drill 1)
  other vias: 62.92,44.98
N$47  (via drill 1)
  other vias: 55.34,44.92
N$48  (via drill 1)
  other vias: 56.12,54.07
N$49  (via drill 1)
  other vias: 25.68,44.6
N$50  (via drill 1)
  other vias: 30.82,44.16
N$51  (via drill 1)
  other vias: 15.13,25.99
N$52  (via drill 1)
  other vias: 24.21,24.14
N$53  (via drill 1)
  other vias: 32.1,13.85
N$54  (via drill 1)
  other vias: 32.1,10.29
N$55  (via drill 1)
  other vias: 39.4,15.88
N$56  (via drill 1)
  other vias: 39.09,2.03
N$57  (via drill 1)
  other vias: 60.31,47.4
N$58  (via drill 1)
  other vias: 13.54,47.14
N$59  (via drill 1)
  other vias: 18.81,47.27
N$60  (via drill 1)
  other vias: 13.54,54.77
N$61  (via drill 1)
  other vias: 18.56,54.89
SCK
  Bottom 0.406: NRF24L1.SCK 51.38,29.49 54.85,29.49 arc45 55.08,29.59 55.27,29.78 55.27,38.82 54.94,39.15 arc45 54.71,39.24 44.01,39.24 44.01,38.85 arc-90 43.69,38.53 IC3.22
SENTIDO_DIREITO
  Bottom 0.813: 18.55,58.2 18.55,58.18 | IC3.2 27.42,51.23 arc45 27.19,51.14 21.21,45.16 18.84,45.16 arc-45 18.19,45.37 16.95,46.92
  Bottom 1.016: 16.95,50.2 16.95,46.92
  Bottom 1.27: U1.5 8.7,40.08 4.76,44.02 4.76,60.12 8.93,63.81 12.43,63.81 18.55,58.2 | 18.55,58.18 20.83,55.58 20.83,54.08 16.95,50.2
SENTIDO_ESQUERDO
  Bottom 0.61: IC3.3 arc45 33.3,48.74 32.32,49.71 28.71,49.71 arc45 28.48,49.62 arc45 28.34,49.68 27.5,49.68 22.57,44.75 arc45 22.48,44.53 | U1.10 15.4,33.73 arc45 16.26,33.95
  Bottom 0.813: 33.05,48.83 arc-45 33.28,48.73 IC3.3
  Bottom 1.016: 22.48,40.3 22.48,44.53
  Bottom 1.27: 16.26,33.95 22.48,40.3
VCC_3,4
  Bottom 0.4: 40.99,33.3 41.04,33.3 49.54,33.3 | 39.86,52.5 44.66,52.5
  Bottom 0.406: NRF24L1.VCC 49.2,37.11 arc-90 49.51,36.79 49.54,33.3 | 40.99,33.3 arc-45 40.99,33.46 38.05,33.44 arc-45 37.83,33.53 37.81,33.55 37.81,50.12 arc-45 38.16,51.59 39.86,52.5 | 44.66,52.5 arc44 44.73,52.51 | 41.04,33.3 arc-90 40.93,33.41
  Bottom 0.61: 40.93,33.41 IC3.20
  Bottom 0.813: R10.1 46.41,54.06 arc45 46.19,53.97 44.73,52.51 44.73,50.2 arc45 44.82,49.98 45.62,49.18 arc-45 45.77,49.15 50.48,49.15 52.55,51.34 arc45 52.64,51.56 52.64,55.88 arc-90 52.73,55.98 57.79,55.98 57.79,52.5 arc90 58.11,52.18 67.96,52.18 arc-45 68.19,52.09 70.09,50.18 70.09,47.82 arc-45 70,47.6 | R3.2 arc-45 R3.2 | 60.4,47.41 arc45 R4.2
  Bottom 1.016: LM317.2 42.3,66.07 arc-45 42.08,66.16 41.77,66.46 41.77,69.93 arc45 41.68,70.16 40.98,70.85 38.64,70.85 arc45 38.42,70.76 37.86,70.2 37.38,69.72 37.38,60.98 arc-45 37.29,60.75 31.88,55.4 arc45 31.75,55.22 R9.1 27.88,54.35 arc45 27.66,54.25 R12.1
  Bottom 1.27: LM317.2 44.65,66.07 arc45 44.36,66.03 | C9.+ arc-45 37.61,70.71 37.61,70.78 37.77,70.62 arc-45 37.86,70.39 37.86,70.2 | 42.08,66.16 41.91,66 arc45 41.82,65.77 41.82,61.78 44.03,59.58 arc-45 44.12,59.35 R6.2 46.51,56.75 arc-45 46.74,56.66 R5.2 | R5.2 arc90 47.37,55.62 R10.1 | R5.2 47.58,55.93 arc-45 47.67,56.16 50.87,59.36 arc-45 51.09,59.45 C8.+ | 70,47.6 67.38,44.98 R3.2 | R3.2 60.4,47.41
  Bottom 1.676: D2.C 59.04,46.08 arc-45 59.13,46.3 R4.2
VCC_7,4  (via drill 0.6)
  Top 1.27: v19.52,41.36 v25.15,56.57
  Bottom 1.27: 15.45,38.96 15.45,38.91 U1.6 15.19,38.98 14.86,38.98 10.88,35 U1.9 | B3.+ 12.83,47.13 12.83,42.35 14.52,41.35 U1.4 v19.52,41.36 | U1.11 9,32.46 arc45 8.78,32.37 6.07,29.66 6.13,14.28 arc45 6.29,14.12 8.87,11.61 18.77,11.65 arc46 19.14,11.68 19.66,12.15 19.66,21.02 arc45 19.57,21.25 B4.+ | LM317.3 44.41,70.44 arc45 44.31,70.67 42.18,72.47 33.55,72.47 arc45 33.27,72.38 30.92,70.12 30.92,62.77 arc-45 30.83,62.35 v25.15,56.57 | C10.+ 54.91,68.67 arc-45 C11.+ 55.2,68.65 arc-45 55.31,68.61
  Bottom 1.422: LM317.3 55.31,68.61 55.85,68.61 arc-45 56.07,68.51 60.7,63.89 66.19,63.89 arc45 66.41,63.98 ALIMENTACAO_ACIONAMENTO.+
  Bottom 1.676: U1.11 U1.9 | 15.45,38.96 15.36,39.06 U1.4

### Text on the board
Bottom: Luana | Rosana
